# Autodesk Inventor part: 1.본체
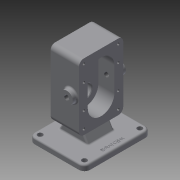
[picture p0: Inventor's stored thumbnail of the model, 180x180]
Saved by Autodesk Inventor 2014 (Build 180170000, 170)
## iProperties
Created: 2020-04
Part Number: 1.본체
Material: Generic
Document SubType Name: Modeling
Designer: kh
Density: 1 g/cm^3
Appearance: Default
Mass: 544.812 g
Surface Area: 819.925 cm^2
Volume: 544.812 cm^3
Author: kh
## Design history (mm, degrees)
sketch "스케치1"
  geometry: L1 (-50, -60)-(50, -60); L2 (50, -60)-(50, 60); L3 (50, 60)-(-50, 60); L4 (-50, 60)-(-50, -60); L5 (-50, -60)-(50, 60); L6 (50, -60)-(-50, 60); 1 further point
  constraints: 12 end point, 2 midpoint, 2 parallel, 1 horizontal, 1 perpendicular
  dimensions: "d0" = 100 distance of L2.end L3.end; "d1" = 120 distance of L1.end L2.end
extrude "돌출1" new body sketch "스케치1" distance "d2" = 10; taper "d3" = 0 deg
sketch "스케치2"
  geometry: L1 (-20, 150)-(33, 150); L2 (33, 150)-(33, 30); L3 (33, 30)-(-20, 30); L4 (-20, 30)-(-20, 150); L5 (50, 0)-(50, 10) reference; 1 further point
  constraints: 8 end point, 2 parallel, 1 horizontal, 1 perpendicular
  dimensions: "d4" = 53 distance of L1.start L1.end; "d5" = 120 distance of L3.end L1.start; "d6" = 17 distance between parallel lines of L5 L2; "d7" = 150 distance from line of point (0, 0) L1
extrude "돌출2" join sketch "스케치2" stored distance "d8" = 80; taper "d9" = 0 deg
sketch "스케치3"
  geometry: L1 (0, 80)-(0, 0) reference; L2 (-120, 80)-(0, 80) reference; L3 (-120, 80)-(-120, 0) reference; L4 (0, 0)-(-120, 0) reference; L5 (-60, 0)-(-60, 102.442); L6 (-150, 40)-(-86.729, 40); C1 r 19 at (-38, 40)
  constraints: 4 end point, 2 perpendicular, 1 centre point, 1 midpoint, 1 point on line
  dimensions: "d10" = 22 distance from line of L5 C1.centre; "d11" = 38 diameter of C1
extrude "돌출3" join sketch "스케치3" distance "d12" = 17; taper "d13" = 0 deg
sketch "스케치4"
  geometry: L1 (-82, 40)-(-38, 40); L2 (-82, 16)-(-38, 16); L3 (-38, 64)-(-82, 64); L4 (-120, 80)-(0, 80) reference; L5 (0, 80)-(0, 0) reference; L6 (0, 40)-(-36.841, 40); L7 (-60, 80)-(-60, -7.425); A1 r 24 centre (-82, 40) between (-82, 64) and (-82, 16); A2 r 24 centre (-38, 40) between (-38, 16) and (-38, 64); 2 further points
  constraints: 12 end point, 4 point on circle, 4 tangent, 3 midpoint, 2 centre point, 2 perpendicular, 2 point on line, 1 horizontal, 1 parallel
  dimensions: "d14" = 24 radius of A1; "d15" = 44 distance of L1.start L1.end
extrude "돌출4" cut sketch "스케치4" distance "d16" = 29; taper "d17" = 0 deg
sketch "스케치5"
  geometry: L1 (-38, 16)-(-82, 16) reference; L2 (-82, 64)-(-38, 64) reference; C1 r 12.5 at (-82, 40); C2 r 12.5 at (-38, 40); A1 r 24 centre (-38, 40) between (-38, 16) and (-38, 64) reference; A2 r 24 centre (-82, 40) between (-82, 64) and (-82, 16) reference; 1 further point
  constraints: 2 centre point, 2 coincident
  dimensions: "d18" = 25 diameter of C1; "d19" = 25 diameter of C2
extrude "돌출5" cut sketch "스케치5" distance "d20" = 15; taper "d21" = 0 deg
sketch "스케치6"
  geometry: C1 r 19 at (0, 0) reference; C2 r 8.5 at (0, 0); 1 further point
  constraints: 1 centre point, 1 coincident
  dimensions: "d22" = 17 diameter of C2
extrude "돌출6" cut sketch "스케치6" stored distance "d23" = 15; taper "d24" = 0 deg
sketch "스케치7"
  geometry: C1 r 8.5 at (0, 0) reference; C2 r 14 at (0, 0); 1 further point
  constraints: 1 centre point, 1 coincident
  dimensions: "d25" = 28 diameter of C2
extrude "돌출7" cut sketch "스케치7" distance "d26" = 7.3; taper "d27" = 0 deg
fillet "모깎기1" dims "d28" = 0.5
chamfer "모따기1" distance "d29" = 0.7; stored, may be unused: second distance "d30" = 2, angle "d31" = 30 deg
sketch "스케치8"
  geometry: L1 (20, -150)-(20, -30) reference; L2 (20, -90)-(-83.121, -90); C1 r 11 at (6, -90); 2 further points
  constraints: 2 end point, 1 centre point, 1 coincident, 1 midpoint, 1 perpendicular, 1 point on line
  dimensions: "d32" = 14 distance from line of point (6, -90) L1; "d33" = 22 diameter of C1
extrude "돌출8" join sketch "스케치8" distance "d34" = 8; taper "d35" = 0 deg
hole "구멍1" diameter "d38" = 8.917; stored, may be unused: countersink angle "d42" = 90 deg, drill point angle "d44" = 118 deg; dims "d36" = 10, "d37" = 10, "d39" = 6, "d40" = 4, "d41" = 2, "d43" = 8
fillet "모깎기2" dims "d45" = 10
sketch "스케치10"
  geometry: L1 (-50, 50)-(-50, -50) reference; L2 (40, 60)-(-40, 60) reference; L3 (50, -50)-(50, 50) reference; L4 (-40, -60)-(40, -60) reference; A1 r 10 centre (-40, -50) between (-50, -50) and (-40, -60) reference; A2 r 10 centre (-40, 50) between (-40, 60) and (-50, 50) reference; A3 r 10 centre (40, 50) between (50, 50) and (40, 60) reference; A4 r 10 centre (40, -50) between (40, -60) and (50, -50) reference; 1 further point
hole "구멍2" sketch "스케치10" at (40, 50), (-40, 50), (40, -50), (-40, -50) diameter "d46" = 9; stored, may be unused: countersink angle "d50" = 90 deg, drill point angle "d52" = 118 deg; dims "d47" = 6, "d48" = 4, "d49" = 2, "d51" = 8
sketch "스케치11"
  geometry: L1 (-33, 24)-(20, 24); L2 (20, 24)-(20, -24); L3 (20, -24)-(-33, -24); L4 (-33, -24)-(-33, 24); L5 (-50, 50)-(-50, -50) reference; L6 (0, 0)-(115.553, 0); 1 further point
  constraints: 10 end point, 2 parallel, 2 perpendicular, 1 horizontal, 1 midpoint, 1 point on line
  dimensions: "d53" = 48 distance of L1.end L2.end; "d54" = 53 distance of L1.start L1.end; "d55" = 17 distance between parallel lines of L5 L4
extrude "돌출9" join sketch "스케치11" stored distance "d56" = 8; taper "d57" = 0 deg
sketch "스케치12"
  geometry: L1 (53, -20)-(0, -20) reference; L2 (53, 0)-(53, -20) reference; L3 (0, 0)-(53, 0) reference; L4 (0, 0)-(0, -20) reference; L5 (53, 0)-(41.453, -20); L6 (11.547, -20)-(0, 0); L7 (41.453, -20)-(53, -20); L8 (53, -20)-(53, 0); L9 (11.547, -20)-(0, -20); L10 (0, 0)-(0, -20); 1 further point
  constraints: 12 end point, 4 collinear, 2 point on line
  dimensions: "d58" = 60 deg angle of L5 L3; "d59" = 60 deg angle of L3 L6
extrude "돌출10" cut sketch "스케치12" stored distance "d60" = 8; taper "d61" = 0 deg
fillet "모깎기3" dims "d62" = 9
sketch "스케치13"
  geometry: L1 (0, 62)-(0, 0) reference; L2 (-111, 71)-(-9, 71) reference; L3 (-120, 0)-(-120, 62) reference; L4 (-9, -9)-(-111, -9) reference; L5 (-38, 7)-(-82, 7) reference; L6 (-82, 55)-(-38, 55) reference; A1 r 9 centre (-9, 0) between (-9, -9) and (0, 0) reference; A2 r 9 centre (-9, 62) between (0, 62) and (-9, 71) reference; A3 r 9 centre (-111, 62) between (-111, 71) and (-120, 62) reference; A4 r 9 centre (-111, 0) between (-120, 0) and (-111, -9) reference; A5 r 24 centre (-82, 31) between (-82, 55) and (-82, 7) reference; A6 r 24 centre (-38, 31) between (-38, 7) and (-38, 55) reference; 9 further points
  constraints: 5 horizontal alignment, 3 coincident, 2 vertical alignment
  dimensions: "d63" = 44 distance of point (-38, 62) point (-82, 62); "d64" = 29 distance of point (-82, 62) point (-111, 62); "d65" = 102 distance of point (-9, 62) point (-111, 62)
hole "구멍3" sketch "스케치13" at (-111, 62), (-82, 62), (-38, 62), (-9, 62), (-111, 0), (-82, 0), (-38, 0), (-9, 0) diameter "d66" = 4.459; stored, may be unused: countersink angle "d70" = 90 deg, drill point angle "d72" = 118 deg; dims "d67" = 10, "d68" = 4, "d69" = 2, "d71" = 12
fillet "모깎기4" dims "d73" = 3
fillet "모깎기5" dims "d74" = 3
fillet "모깎기6" dims "d75" = 3
chamfer "모따기2" distance "d76" = 1; stored, may be unused: second distance "d77" = 2, angle "d78" = 30 deg
sketch "스케치14"
  geometry: L1 (36.998, -20.739)-(36.998, 20.739); L2 (36.998, 20.739)-(43.002, 20.739); L3 (43.002, 20.739)-(43.002, -20.739); L4 (43.002, -20.739)-(36.998, -20.739); L5 (43.002, -20.739)-(36.998, 20.739); L6 (36.998, -20.739)-(43.002, 20.739); L7 (50, -50)-(50, 50) reference; L8 (-40, -60)-(40, -60) reference; 2 further points
  constraints: 4 end point, 1 midpoint, 2 other
  dimensions: "d79" = 10 distance from line of L7 point (40, 0); "d80" = 60 distance from line of point (40, 0) L8
feature "엠보싱1" sketch "스케치14" dims "d0" = 100, "d1" = 120, "d81" = 0.5, "d82" = 0
node "솔리드1"
mirror "대칭1"
node "투영된 루프1"
node "투영된 루프2"
node "투영된 루프3"
node "투영된 루프5"
node "투영된 루프6"
node "투영된 루프7"
